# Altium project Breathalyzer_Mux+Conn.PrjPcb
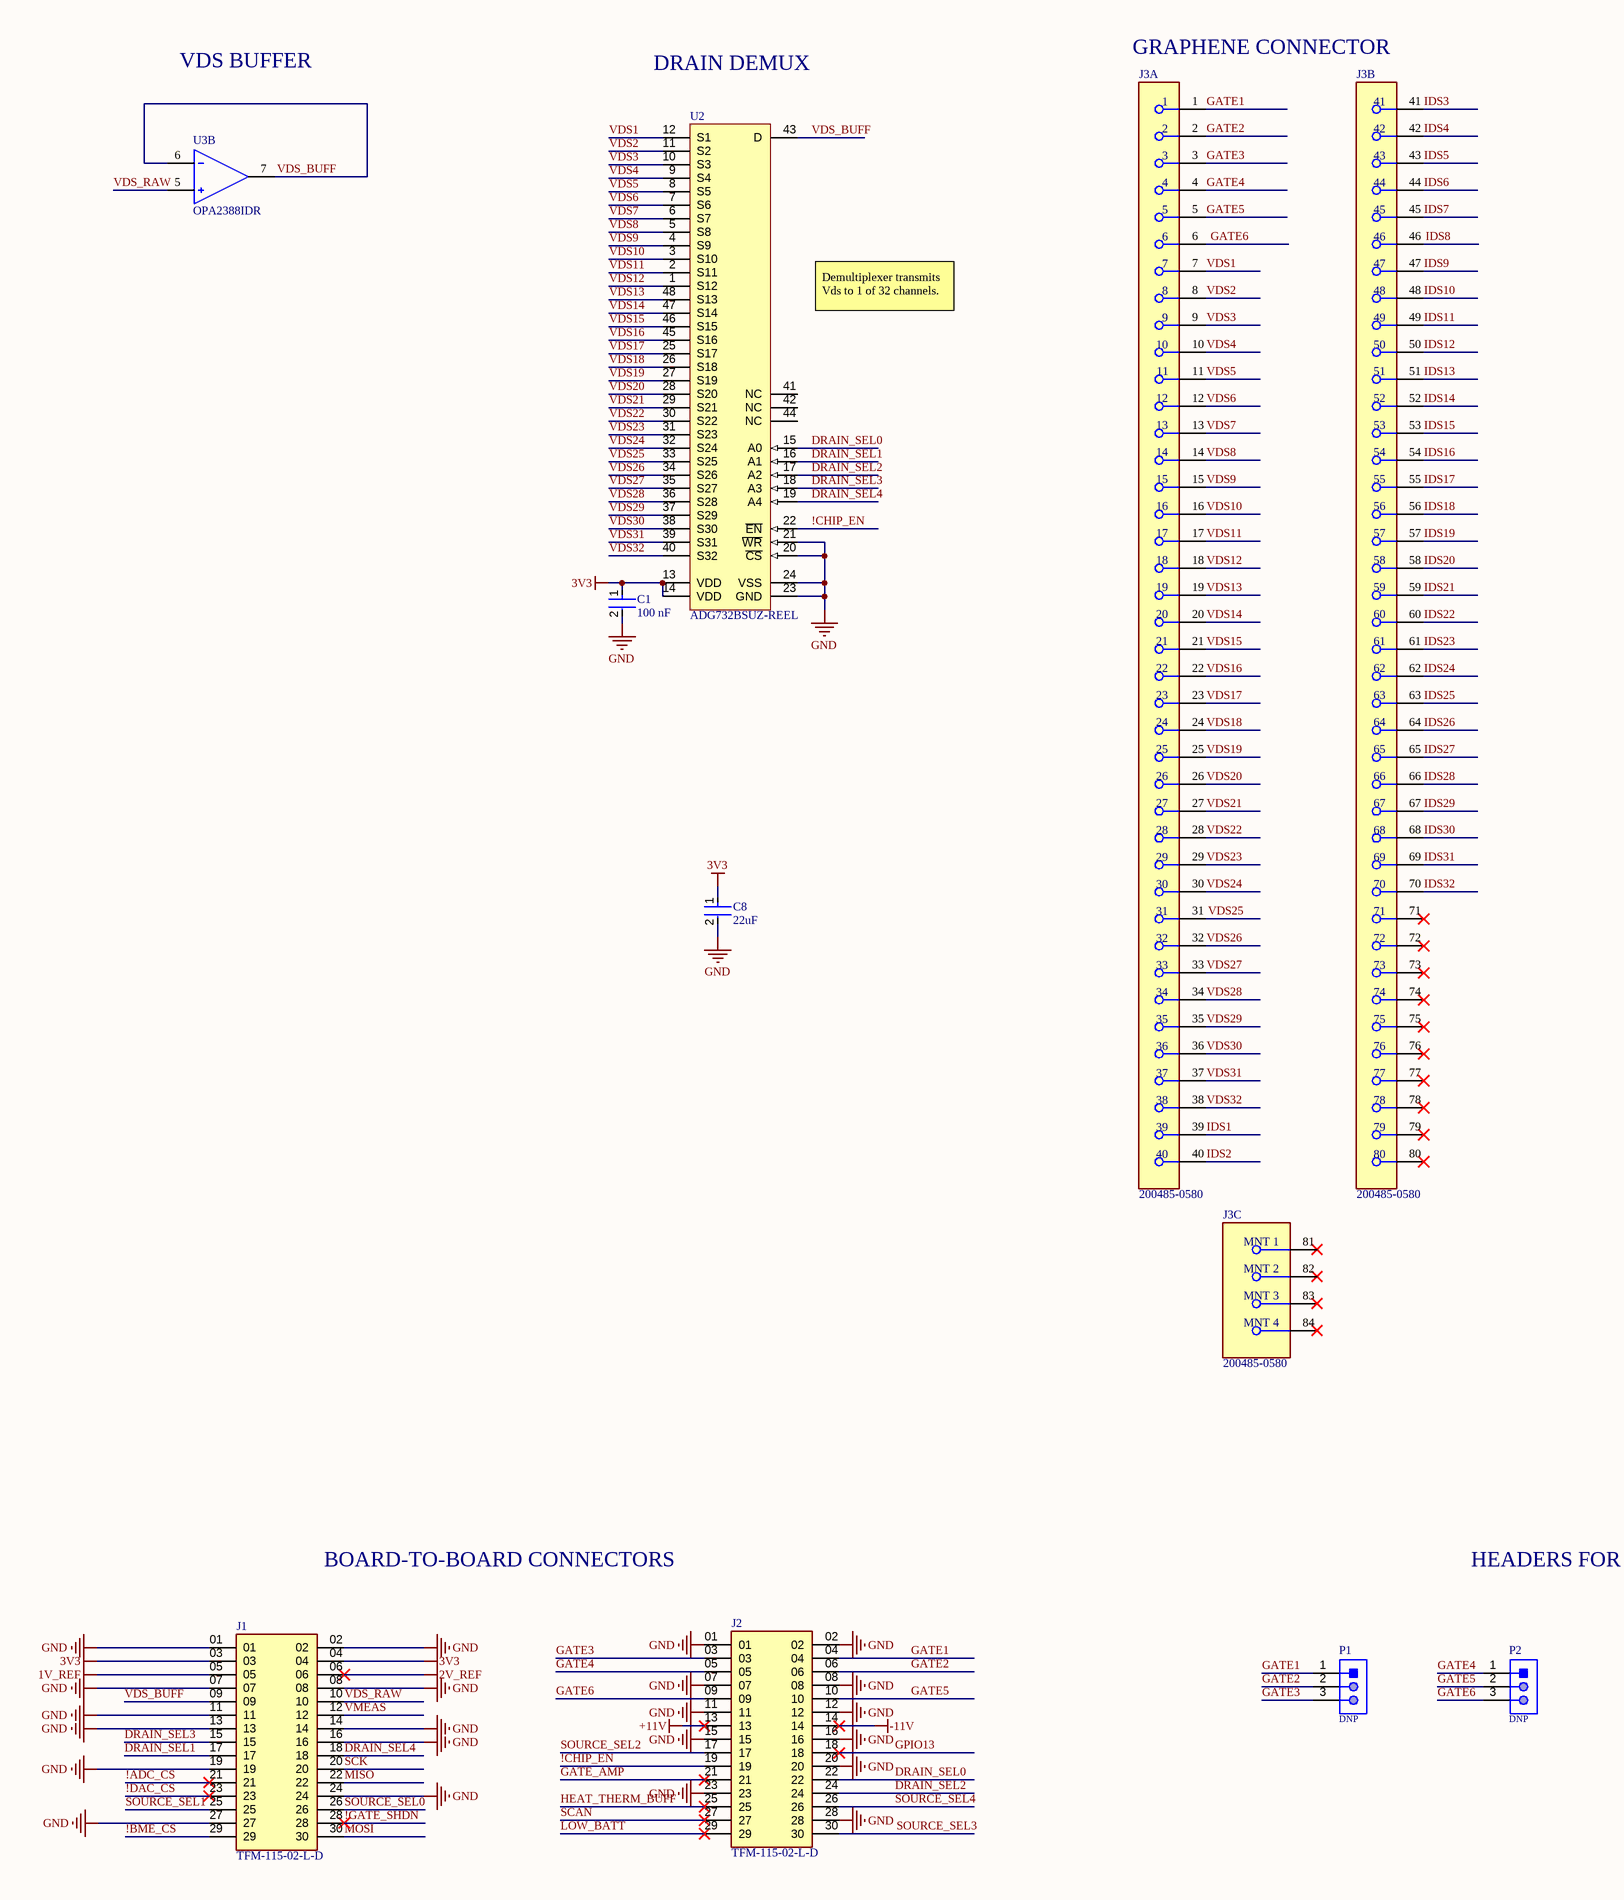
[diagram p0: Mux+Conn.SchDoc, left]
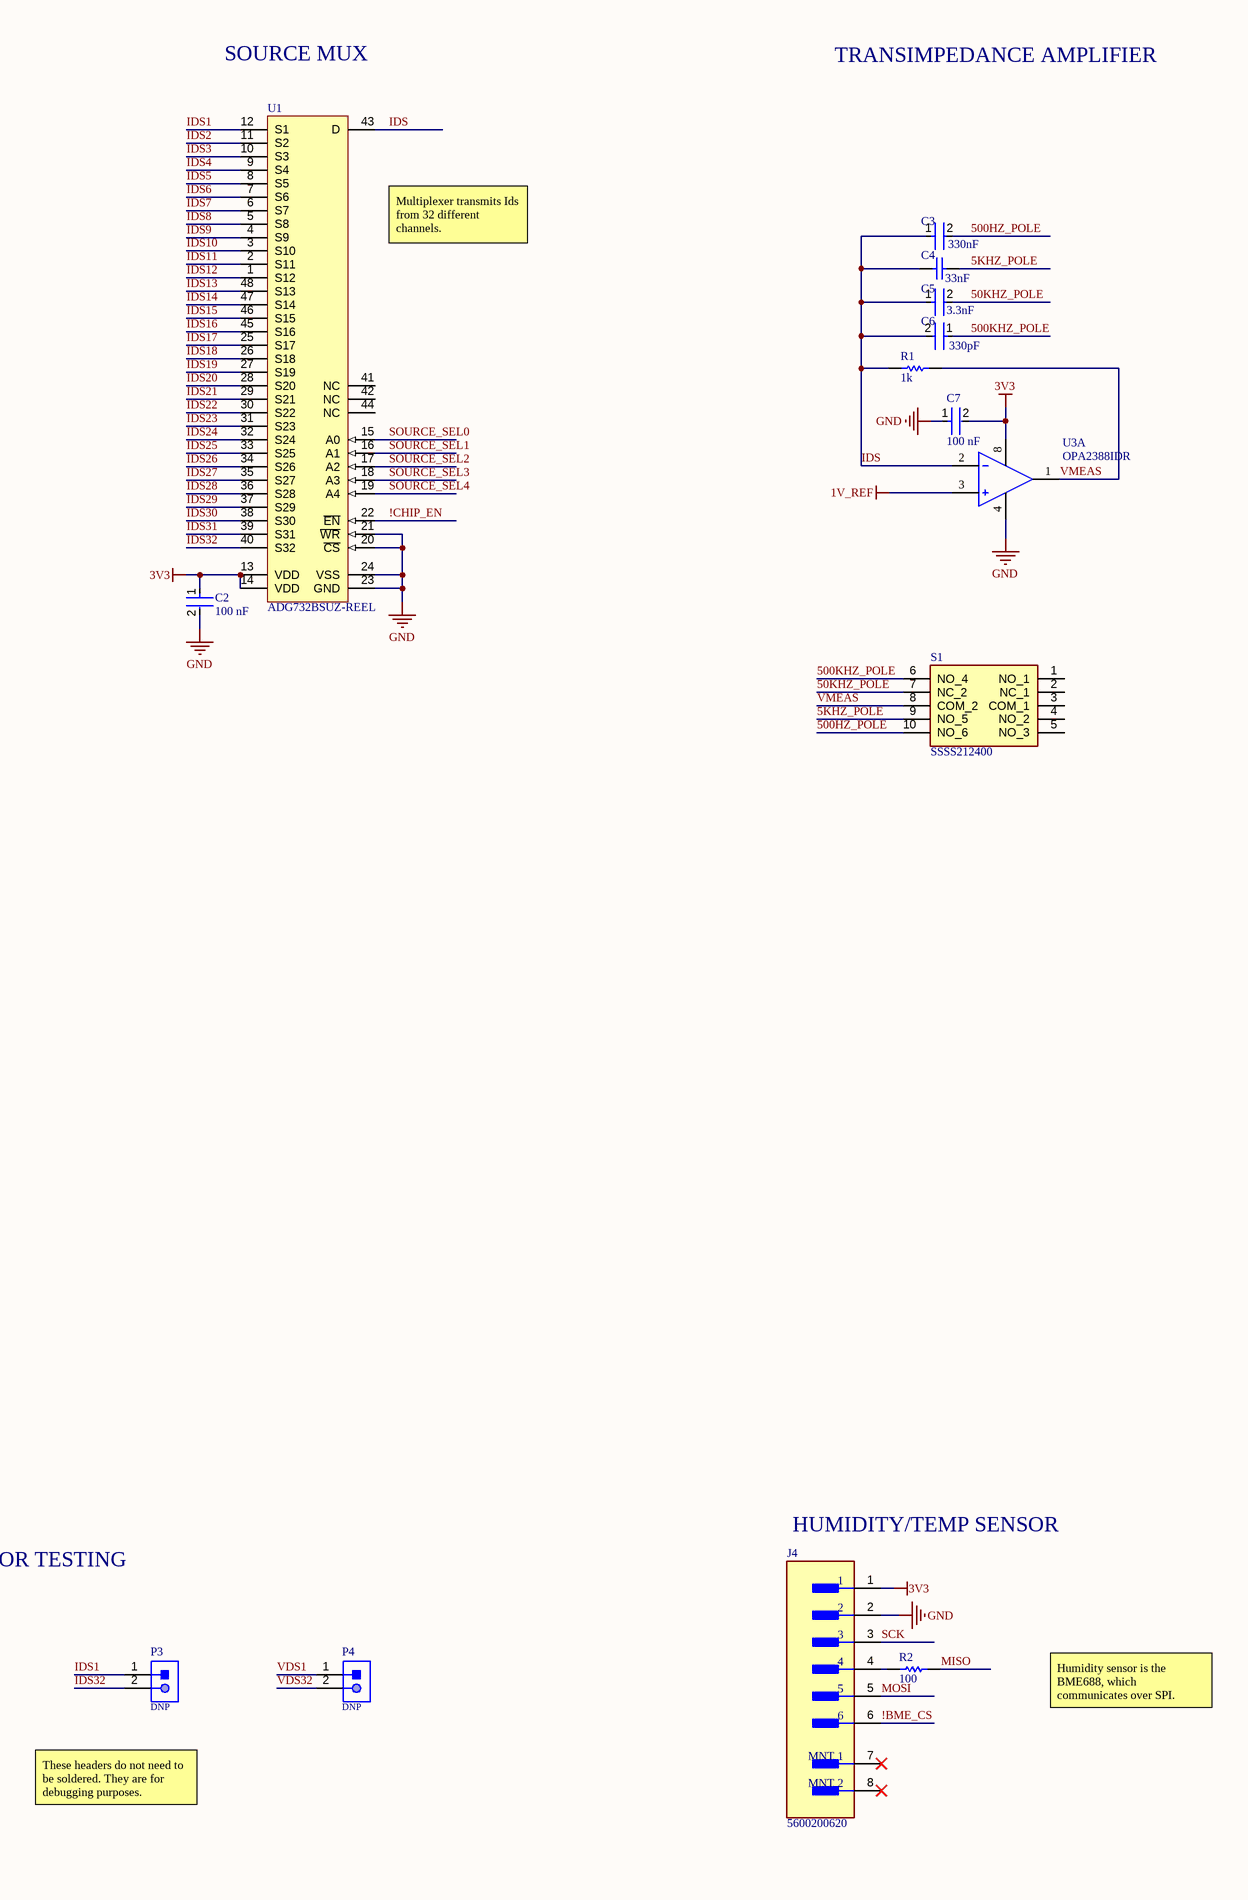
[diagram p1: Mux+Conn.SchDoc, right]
CAGE_CODE: ?????; CONTRACT_NUMBER: <CONTRACT NO>; DOC_NO_ASSY_DWG: <ASSY DWG NO>; DOC_NO_BOM: <BOM DOC NO>; DOC_NO_FAB_DWG: <FAB DWG NO>; DOC_NO_SCH_DWG: <SCH DWG NO>; PCB_2_DEC_TOL: +/-.01; PCB_3_DEC_TOL: +/-.010; PCB_ANG_TOL: +/-1/2; PCB_ASSEMBLY_NO: <PCB ASSY NO>; PCB_CHECKER: - -----; PCB_CHECKER_APP_DATE: --/--/----; PCB_DESIGNER: - -----; PCB_DESIGNER_APP_DATE: --/--/----; PCB_DWG_NO: <PCB DWG NO>; PCB_ENGINEER: - -----; PCB_ENGINEER_APP_DATE: --/--/----; PCB_PART_NUMBER: <PCB PN>; PCB_REV: A; SCH_REV: A
1 sheet, 22 parts. Net scope: global (net labels, ports and power ports of the same name join across sheets).
Board file: PCB1.PcbDoc

## Sheet Mux+Conn.SchDoc
size 558 x 431 mm; SheetNumber: 1; SheetTotal: 1; ENG_APP_DATE: --/--/--; DSN_APP_DATE: --/--/--; CHK_APP_DATE: --/--/--

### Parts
C1  100 nF  [FP-C0805C-DN-MFG]
C2  100 nF  [FP-C0805C-DN-MFG]
C3  330nF  [FP-CC0805-0_85-MFG]
C4  33nF  [CAPC2013X95X45NL10T25]
C5  3.3nF  [FP-C0805C-DN-MFG]
C6  330pF  [FP-C0805C-DN-MFG]
C7  100 nF  [FP-C0805C-DN-MFG]
C8  22uF  [FP-GRM32-MFG]
J1  TFM-115-02-L-D  [SAMTEC_TFM-115-02-L-D]
J2  TFM-115-02-L-D  [SAMTEC_TFM-115-02-L-D]
J3  200485-0580  [FP-200485-0580-MFG]  (parts A,B,C of 3)
J4  5600200620  [FP-5600200620-MFG]
P1  DNP  [61300311021]
P2  DNP  [61300311021]
P3  DNP  [61300211021]
P4  DNP  [61300211021]
R1  1k  [RESC2013X55X40LL15T20]
R2  100  [RESC2013X50X30LL20T20]
S1  SSSS212400  [SSSS212400]
U1  ADG732BSUZ-REEL  [ADI-SU-48_N]
U2  ADG732BSUZ-REEL  [ADI-SU-48_N]
U3  OPA2388IDR  [FP-D0008A-IPC_B]  (parts A,B of 2)

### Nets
1V_REF: J1.05 U3.3(+IN_A)
2V_REF: J1.06
3V3: C1.1 C2.1 C7.2 C8.1 J1.03 J1.04 J4.1 U1.13(VDD) U1.14(VDD) U2.13(VDD) U2.14(VDD) U3.8(V+)
+11V: J2.13
-11V: J2.14
GND: C1.2 C2.2 C7.1 C8.2 J1.01 J1.02 J1.07 J1.08 J1.11 J1.13 J1.14 J1.16 J1.19 J1.24 J1.27 J2.01 J2.02 J2.07 J2.08 J2.11 J2.12 J2.15 J2.16 J2.20 J2.23 J2.28 J4.2 U1.20(~{CS}) U1.21(~{WR}) U1.23(GND) U1.24(VSS) U2.20(~{CS}) U2.21(~{WR}) U2.23(GND) U2.24(VSS) U3.4(V-)
5KHZ_POLE: C4.2 S1.9(NO_5)
50KHZ_POLE: C5.2 S1.7(NC_2)
500HZ_POLE: C3.2 S1.10(NO_6)
500KHZ_POLE: C6.1 S1.6(NO_4)
!ADC_CS: J1.21
!BME_CS: J1.29 J4.6
!CHIP_EN: J2.19 U1.22(~{EN}) U2.22(~{EN})
!DAC_CS: J1.23
!GATE_SHDN: J1.28
DRAIN_SEL0: J2.22 U2.15(A0)
DRAIN_SEL1: J1.17 U2.16(A1)
DRAIN_SEL2: J2.24 U2.17(A2)
DRAIN_SEL3: J1.15 U2.18(A3)
DRAIN_SEL4: J1.18 U2.19(A4)
GATE1: J2.04 J3.1 P1.1
GATE2: J2.06 J3.2 P1.2
GATE3: J2.03 J3.3 P1.3
GATE4: J2.05 J3.4 P2.1
GATE5: J2.10 J3.5 P2.2
GATE6: J2.09 J3.6 P2.3
GATE_AMP: J2.21
GPIO13: J2.18
HEAT_THERM_BUFF: J2.25
IDS: C3.1 C4.1 C5.1 C6.2 R1.1 U1.43(D) U3.2(-IN_A)
IDS1: J3.39 P3.1 U1.12(S1)
IDS2: J3.40 U1.11(S2)
IDS3: J3.41 U1.10(S3)
IDS4: J3.42 U1.9(S4)
IDS5: J3.43 U1.8(S5)
IDS6: J3.44 U1.7(S6)
IDS7: J3.45 U1.6(S7)
IDS8: J3.46 U1.5(S8)
IDS9: J3.47 U1.4(S9)
IDS10: J3.48 U1.3(S10)
IDS11: J3.49 U1.2(S11)
IDS12: J3.50 U1.1(S12)
IDS13: J3.51 U1.48(S13)
IDS14: J3.52 U1.47(S14)
IDS15: J3.53 U1.46(S15)
IDS16: J3.54 U1.45(S16)
IDS17: J3.55 U1.25(S17)
IDS18: J3.56 U1.26(S18)
IDS19: J3.57 U1.27(S19)
IDS20: J3.58 U1.28(S20)
IDS21: J3.59 U1.29(S21)
IDS22: J3.60 U1.30(S22)
IDS23: J3.61 U1.31(S23)
IDS24: J3.62 U1.32(S24)
IDS25: J3.63 U1.33(S25)
IDS26: J3.64 U1.34(S26)
IDS27: J3.65 U1.35(S27)
IDS28: J3.66 U1.36(S28)
IDS29: J3.67 U1.37(S29)
IDS30: J3.68 U1.38(S30)
IDS31: J3.69 U1.39(S31)
IDS32: J3.70 P3.2 U1.40(S32)
LOW_BATT: J2.29
MISO: J1.22 R2.2
MOSI: J1.30 J4.5
SCAN: J2.27
SCK: J1.20 J4.3
SOURCE_SEL0: J1.26 U1.15(A0)
SOURCE_SEL1: J1.25 U1.16(A1)
SOURCE_SEL2: J2.17 U1.17(A2)
SOURCE_SEL3: J2.30 U1.18(A3)
SOURCE_SEL4: J2.26 U1.19(A4)
VDS1: J3.7 P4.1 U2.12(S1)
VDS2: J3.8 U2.11(S2)
VDS3: J3.9 U2.10(S3)
VDS4: J3.10 U2.9(S4)
VDS5: J3.11 U2.8(S5)
VDS6: J3.12 U2.7(S6)
VDS7: J3.13 U2.6(S7)
VDS8: J3.14 U2.5(S8)
VDS9: J3.15 U2.4(S9)
VDS10: J3.16 U2.3(S10)
VDS11: J3.17 U2.2(S11)
VDS12: J3.18 U2.1(S12)
VDS13: J3.19 U2.48(S13)
VDS14: J3.20 U2.47(S14)
VDS15: J3.21 U2.46(S15)
VDS16: J3.22 U2.45(S16)
VDS17: J3.23 U2.25(S17)
VDS18: J3.24 U2.26(S18)
VDS19: J3.25 U2.27(S19)
VDS20: J3.26 U2.28(S20)
VDS21: J3.27 U2.29(S21)
VDS22: J3.28 U2.30(S22)
VDS23: J3.29 U2.31(S23)
VDS24: J3.30 U2.32(S24)
VDS25: J3.31 U2.33(S25)
VDS26: J3.32 U2.34(S26)
VDS27: J3.33 U2.35(S27)
VDS28: J3.34 U2.36(S28)
VDS29: J3.35 U2.37(S29)
VDS30: J3.36 U2.38(S30)
VDS31: J3.37 U2.39(S31)
VDS32: J3.38 P4.2 U2.40(S32)
VDS_BUFF: J1.09 U2.43(D) U3.6(-IN_B) U3.7(OUT_B)
VDS_RAW: J1.10 U3.5(+IN_B)
VMEAS: J1.12 R1.2 S1.8(COM_2) U3.1(OUT_A)
NetJ4_4: J4.4 R2.1

Not connected (* = marked no-connect by the designer): J3 71* 72* 73* 74* 75* 76* 77* 78* 79* 80* 81(MNT_1)* 82(MNT_2)* 83(MNT_3)* 84(MNT_4)*; J4 7(MNT_1)* 8(MNT_2)*; S1 1(NO_1) 2(NC_1) 3(COM_1) 4(NO_2) 5(NO_3); U1 41(NC) 42(NC) 44(NC); U2 41(NC) 42(NC) 44(NC)

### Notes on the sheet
- VDS BUFFER
- DRAIN DEMUX
- (near J3) GRAPHENE CONNECTOR
- SOURCE MUX
- TRANSIMPEDANCE AMPLIFIER
- (near U1) Multiplexer transmits Ids from 32 different channels.
- (near U2) Demultiplexer transmits Vds to 1 of 32 channels.
- (near J4) HUMIDITY/TEMP SENSOR
- BOARD-TO-BOARD CONNECTORS
- HEADERS FOR TESTING
- Humidity sensor is the BME688, which communicates over SPI.
- These headers do not need to be soldered. They are for debugging purposes.

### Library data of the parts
C1 C2 C7 = CMP-2007-00279-2: CAP CER 0.1UF 50V X7R 0805; Manufacturer Part Number: C0805C104K5RACTU; Manufacturer: KEMET; Value: 0.10 μF; Tolerance: 0.1; Temperature Coefficient: 30ppm/°C; Material: Ceramic
C3 = CMP-03422-000882-1: Surface Mount Ceramic Multilayer Capacitor 0.33uF 10% X7R 16V 0805 Blister T/R; Manufacturer Part Number: CC0805KKX7R7BB334; Manufacturer: Yageo; Tolerance: 0.1
C4 = CMP-1036-04169-2: Manufacturer: Murata; Part Number: GRM219R71H333KA01D
C5 = CMP-2007-00373-2: CAP CER 3300PF 50V X7R 0805; Manufacturer: KEMET; Manufacturer Part Number: C0805C332K5RACTU; Capacitance: 3,300 pF; Tolerance: 0.1; Material: Ceramic; Temperature Coefficient: 30ppm/°C; Value: 3,300 pF
C6 = CMP-2007-00598-2: CAP CER 330PF 50V C0G/NP0 0805; Manufacturer: KEMET; Manufacturer Part Number: C0805C331J5GACTU; Temperature Coefficient: 30ppm/°C; Tolerance: 0.05; Temperature Characteristic: C0G; Material: Ceramic
C8 = CMP-2000-05458-2: CAP CER 22UF 25V X5R 1210; Manufacturer: Murata Electronics North America; Manufacturer Part Number: GRM32ER61E226KE15L; Possible Substitute: GRM32ER61E226KE15K; Other Names: 490-3889-2; Material: Ceramic; Tolerance: 10%; Description: Multilayer Ceramic Capacitors MLCC - SMD/SMT 1210 22uF 25volts X5R 10%
J1 J2 = TFM-115-02-L-D: MF: Samtec Inc.; System: Connector
J3 = CMP-04775-000018-1: 0.5 ONE-TOUCH ST 80P; System: Connector
J4 = CMP-04776-000066-1: CONN HEADER SMD 6POS 2MM; Manufacturer: Molex; Conn Gender: Male; Conn Orientation: Vertical; Current Rating: 3A; Number Of Contacts: 6; Voltage Rating: 125V
P1 P2 = CMP-1502-01061-1: THT Angled Pin Header WR-PHD, Pitch 2.54 mm, Single Row, 3 pins; Manufacturer: Wurth Elektronik; Pitch: 2.54mm; Contact Resistance: 20mOhm; Gender: Male; Pin Number: 3; Rated Current: 3A; Working Voltage: 250VAC; Withstanding Voltage: 500VAC
P3 P4 = CMP-1502-01059-1: THT Angled Pin Header WR-PHD, Pitch 2.54 mm, Single Row, 2 pins; Manufacturer: Wurth Elektronik; Withstanding Voltage: 500VAC; Gender: Male; Pitch: 2.54mm; Pin Number: 2; Rated Current: 3A; Contact Resistance: 20mOhm; Working Voltage: 250VAC
R1 = CMP-2001-04738-1: TNPW08051K00BEEN; Manufacturer: Vishay Dale
R2 = CMP-2001-04901-1: Manufacturer: Vishay Dale; Part Number: CRCW0805100RFKEA
S1 = SSSS212400: Switch; Manufacturer_Name: ALPS Electric
U1 U2 = CMP-0798-00236-1: 1.8 to 5.5 V / +/-2.5 V, 4 Ohm, 32-Channel Analog Multiplexer, -40 to 85 degC, 48-pin QFP (SU-48), Reel; Manufacturer: Analog Devices; Ron (ohms): 4; Max Analog Signal Range: Vss to Vdd; Bandwidth (Hz): 18M; Supply V Guar Performance: Dual_(+/-2.5V), Single_(+3V), Single_(+5V); t transition (s): 23n
U3 = CMP-04895-000483-1: IC OPAMP ZER-DRIFT 2CIRC 8SOIC; Number of Channels: 2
